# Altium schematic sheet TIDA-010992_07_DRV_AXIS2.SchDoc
size 431 x 279 mm; Date: Not shown in title block; ApprovedBy: Not shown in title block; CheckedBy: Not shown in title block; Author: Not shown in title block; CompanyName: Not shown in title block; Engineer: Not shown in title block; Organization: Not shown in title block; Address1: Not shown in title block; Address2: Not shown in title block; Address3: Not shown in title block; Address4: Not shown in title block; DocumentNumber: 7; Revision: Use project parameter SCH_Rev; SheetNumber: 7; SheetTotal: 13; PageSetup: Record=PageOptions¦CenterHorizontal=True¦CenterVertical=True¦PrintScale=1.00¦XCorrection=1.00¦YCorrection=1.00¦PrintKind=0¦BorderSize=5000000¦LeftOffset=0¦BottomOffset=0¦Orientation=2¦PaperLength=1000¦PaperWidth=1000¦Scale=100¦PaperSource=15¦PrintQuality=600¦MediaType=1¦DitherType=10¦PaperKind=Letter¦PrintScaleMode=1
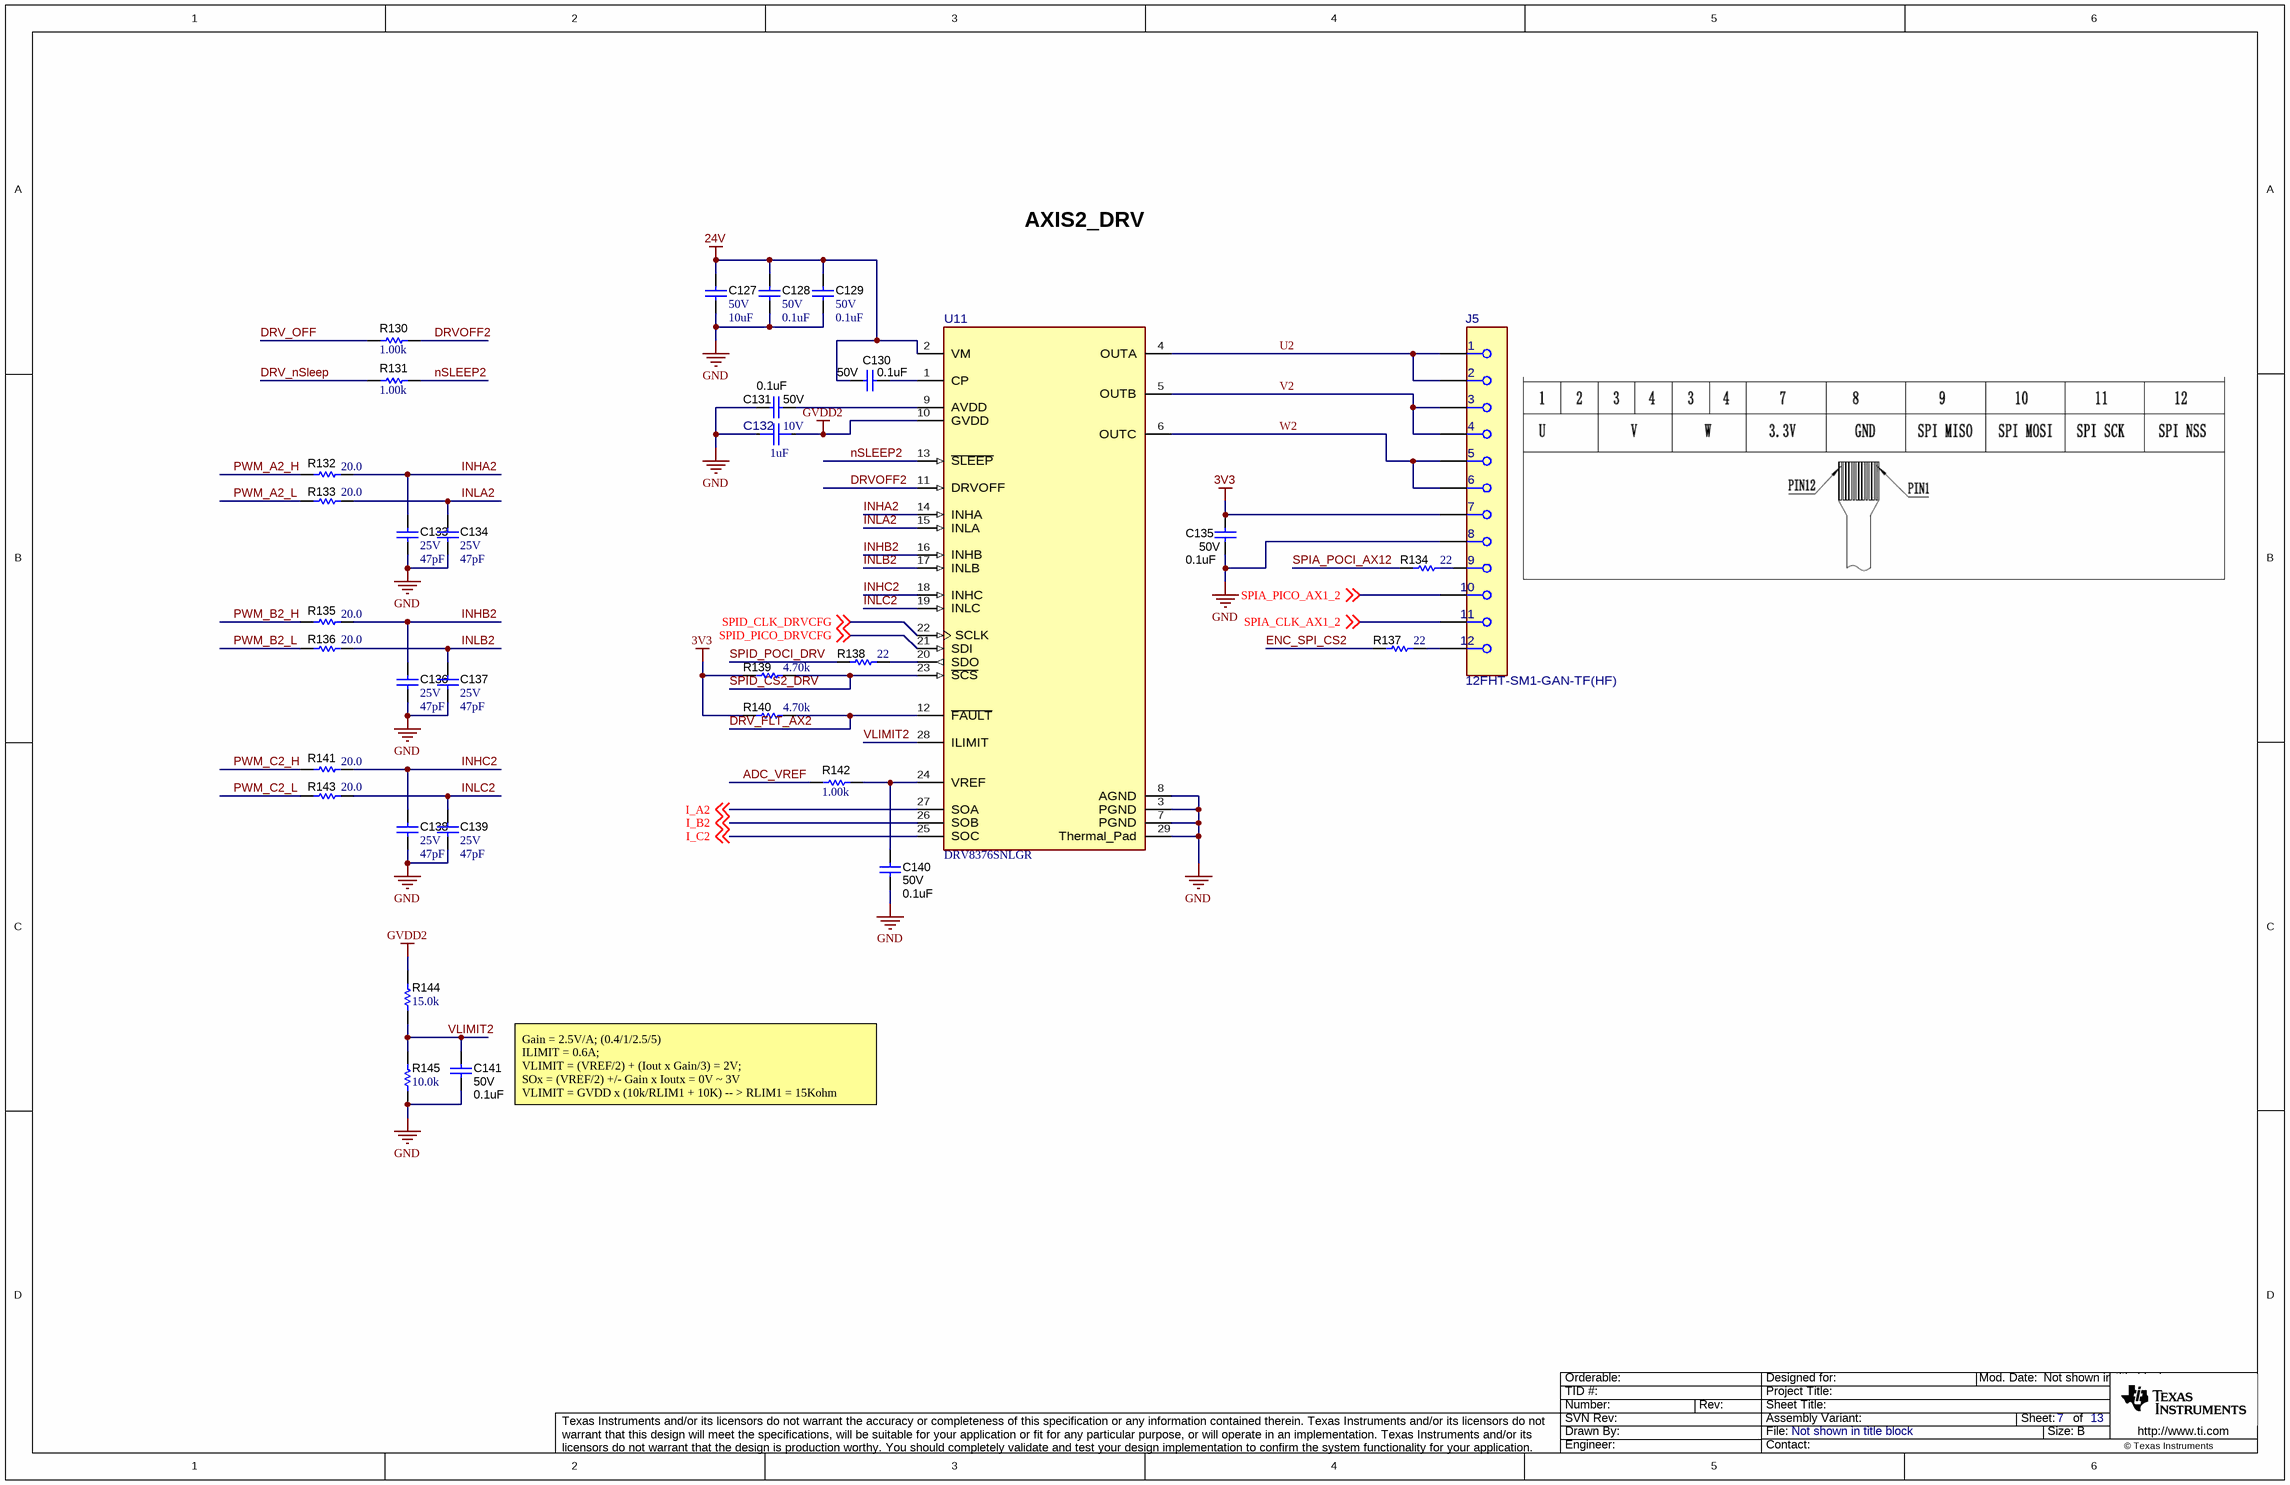
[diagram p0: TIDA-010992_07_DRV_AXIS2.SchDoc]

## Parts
C127  VDC_V: 50V  ValueDisplayed: 10uF  [1206_180]  (hidden comment: CL31B106KBHNNNE)
C128  VDC_V: 50V  ValueDisplayed: 0.1uF  [0402]  (hidden comment: C1005X7R1H104K050BE)
C129  VDC_V: 50V  ValueDisplayed: 0.1uF  [0402]  (hidden comment: C1005X7R1H104K050BE)
C130  VDC_V: 50V  ValueDisplayed: 0.1uF  [0402]  (hidden comment: CGA2B3X7R1H104M050BB)
C131  VDC_V: 50V  ValueDisplayed: 0.1uF  [0402]  (hidden comment: CGA2B3X7R1H104M050BB)
C132  VDC_V: 10V  ValueDisplayed: 1uF  [FP-GMC04X7R105K10NT_0402-MFG]  (hidden comment: GMC04X7R105K10NT)
C133  VDC_V: 25V  ValueDisplayed: 47pF  [0201_033]  (hidden comment: GRM0335C1E470JA01D)
C134  VDC_V: 25V  ValueDisplayed: 47pF  [0201_033]  (hidden comment: GRM0335C1E470JA01D)
C135  VDC_V: 50V  ValueDisplayed: 0.1uF  [0402]  (hidden comment: CGA2B3X7R1H104M050BB)
C136  VDC_V: 25V  ValueDisplayed: 47pF  [0201_033]  (hidden comment: GRM0335C1E470JA01D)
C137  VDC_V: 25V  ValueDisplayed: 47pF  [0201_033]  (hidden comment: GRM0335C1E470JA01D)
C138  VDC_V: 25V  ValueDisplayed: 47pF  [0201_033]  (hidden comment: GRM0335C1E470JA01D)
C139  VDC_V: 25V  ValueDisplayed: 47pF  [0201_033]  (hidden comment: GRM0335C1E470JA01D)
C140  VDC_V: 50V  ValueDisplayed: 0.1uF  [0402]  (hidden comment: CGA2B3X7R1H104M050BB)
C141  VDC_V: 50V  ValueDisplayed: 0.1uF  [0402]  (hidden comment: CGA2B3X7R1H104M050BB)
J5  12FHT-SM1-GAN-TF(HF)  [FP-12FHT-SM1-GAN-TF(HF)_CONN_FPC_12-MFG]
R130  ValueDisplayed: 1.00k  [0402]  (hidden comment: CRCW04021K00FKED)
R131  ValueDisplayed: 1.00k  [0402]  (hidden comment: CRCW04021K00FKED)
R132  ValueDisplayed: 20.0  [0201_033]  (hidden comment: CRCW020120R0FNED)
R133  ValueDisplayed: 20.0  [0201_033]  (hidden comment: CRCW020120R0FNED)
R134  ValueDisplayed: 22  [0201]  (hidden comment: ERJ-1GNJ220C)
R135  ValueDisplayed: 20.0  [0201_033]  (hidden comment: CRCW020120R0FNED)
R136  ValueDisplayed: 20.0  [0201_033]  (hidden comment: CRCW020120R0FNED)
R137  ValueDisplayed: 22  [0201]  (hidden comment: ERJ-1GNJ220C)
R138  ValueDisplayed: 22  [0201]  (hidden comment: ERJ-1GNJ220C)
R139  ValueDisplayed: 4.70k  [0201]  (hidden comment: RC0201FR-7D4K7L)
R140  ValueDisplayed: 4.70k  [0201]  (hidden comment: RC0201FR-7D4K7L)
R141  ValueDisplayed: 20.0  [0201_033]  (hidden comment: CRCW020120R0FNED)
R142  ValueDisplayed: 1.00k  [0402]  (hidden comment: CRCW04021K00FKED)
R143  ValueDisplayed: 20.0  [0201_033]  (hidden comment: CRCW020120R0FNED)
R144  ValueDisplayed: 15.0k  [0402]  (hidden comment: RC0402FR-0715KL)
R145  ValueDisplayed: 10.0k  [0402L]  (hidden comment: CRCW040210K0FKED)
U11  DRV8376SNLGR  [NLG0028A-MFG]

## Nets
3V3: C135.2 J5.7 R139.2 R140.2
24V: C127.1 C128.1 C129.1 C130.1 U11.2(VM)
GND: C127.2 C128.2 C129.2 C131.1 C132.1 C133.2 C134.2 C135.1 C136.2 C137.2 C138.2 C139.2 C140.1 C141.1 J5.8 R145.1 U11.3(PGND) U11.7(PGND) U11.8(AGND) U11.29(Thermal_Pad)
GVDD2: C132.2 R144.2 U11.10(GVDD)
ADC_VREF: R142.1
DRV_FLT_AX2: R140.1 U11.12(~{FAULT})
DRV_nSleep: R131.1
DRV_OFF: R130.1
DRVOFF2: R130.2 U11.11(DRVOFF)
ENC_SPI_CS2: R137.1
I_A2: U11.27(SOA) ; off-sheet I_A2
I_B2: U11.26(SOB) ; off-sheet I_B2
I_C2: U11.25(SOC) ; off-sheet I_C2
INHA2: C133.1 R132.2 U11.14(INHA)
INHB2: C136.1 R135.2 U11.16(INHB)
INHC2: C138.1 R141.2 U11.18(INHC)
INLA2: C134.1 R133.2 U11.15(INLA)
INLB2: C137.1 R136.2 U11.17(INLB)
INLC2: C139.1 R143.2 U11.19(INLC)
nSLEEP2: R131.2 U11.13(~{SLEEP})
PWM_A2_H: R132.1
PWM_A2_L: R133.1
PWM_B2_H: R135.1
PWM_B2_L: R136.1
PWM_C2_H: R141.1
PWM_C2_L: R143.1
SPIA_CLK_AX1_2: J5.11 ; off-sheet SPIA_CLK_AX1_2
SPIA_PICO_AX1_2: J5.10 ; off-sheet SPIA_PICO_AX1_2
SPIA_POCI_AX12: R134.1
SPID_CLK_DRVCFG: U11.22(SCLK) ; off-sheet SPID_CLK_DRVCFG
SPID_CS2_DRV: R139.1 U11.23(~{SCS})
SPID_PICO_DRVCFG: U11.21(SDI) ; off-sheet SPID_PICO_DRVCFG
SPID_POCI_DRV: R138.1
U2: J5.1 J5.2 U11.4(OUTA)
V2: J5.3 J5.4 U11.5(OUTB)
VLIMIT2: C141.2 R144.1 R145.2 U11.28(ILIMIT)
W2: J5.5 J5.6 U11.6(OUTC)
NetC130_2: C130.2 U11.1(CP)
NetC131_2: C131.2 U11.9(AVDD)
NetC140_2: C140.2 R142.2 U11.24(VREF)
NetJ5_9: J5.9 R134.2
NetJ5_12: J5.12 R137.2
NetR138_2: R138.2 U11.20(SDO)

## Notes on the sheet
- AXIS2_DRV
- Gain = 2.5V/A; (0.4/1/2.5/5)
  ILIMIT = 0.6A;
  VLIMIT = (VREF/2) + (Iout x Gain/3) = 2V;
  SOx = (VREF/2) +/- Gain x Ioutx = 0V ~ 3V
  VLIMIT = GVDD x (10k/RLIM1 + 10K) -- > RLIM1 = 15Kohm

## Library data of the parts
C127 = CMP-0008802-2: CAP, CERM, 10 uF, 50 V, +/- 10%, X7R, 1206; Manufacturer: Samsung; TaMin_C: -55°C; Polarized: N; SizeAreaWB_mm2: 10.92; Value1: Unknown; U/M: EA; Value: 10uF; TaMax_C: 125°C; SizeZ_mm: 1.8; SizeX_mm: 3.2; SizeY_mm: 1.6; Cap_Case: 1206; SizeArea_mm2: 5.12; Cap_F: 10µF; AEC Category: Q200
C128 C129 = CMP-0064946-2: CAP, CERM, 0.1 uF, 50 V,+/- 10%, X7R, 0402; Manufacturer: TDK; TaMin_C: -55°C; Polarized: N; SizeAreaWB_mm2: 3; Value1: Unknown; U/M: EA; Value: 0.1uF; TaMax_C: 125°C; SizeZ_mm: 0.6; SizeX_mm: 1; SizeY_mm: 0.5; Cap_F: 100nF; AEC Category: Q200
C130 C131 C135 C140 C141 = CMP-0006326-2: CAP, CERM, 0.1 uF, 50 V, +/- 20%, X7R, AEC-Q200 Grade 1, 0402; Manufacturer: TDK; TaMin_C: -55°C; Polarized: N; SizeAreaWB_mm2: 3; Value1: Unknown; U/M: EA; Value: 0.1uF; TaMax_C: 125°C; SizeZ_mm: 0.6; SizeX_mm: 1; SizeY_mm: 0.5; AEC Qualified: Y; Cap_F: 100nF; AEC Category: Q200
C132 = CMP-0093200-1: 1µF ±10% 10V Ceramic Capacitor X7R 0402 (1005 Metric); Manufacturer: Cal-Chip Electronics; TempCo: 15%; SizeZ_mm: 0.6mm; AEC Qualified: No
C133 C134 C136-C139 = CMP-0009662-3: CAP, CERM, 47 pF, 25 V, +/- 5%, C0G/NP0, 0201; Manufacturer: MuRata; TaMin_C: -55°C; Polarized: N; SizeAreaWB_mm2: 2.08; Value1: Unknown; U/M: EA; Value: 47pF; TaMax_C: 125°C; SizeZ_mm: 0.33; SizeX_mm: 0.6; SizeY_mm: 0.3; Cap_Case: 0201; SizeArea_mm2: 0.18; AEC Category: Q200
J5 = CMP-0126588-1: Conn FPC Connector F 12 POS 0.5mm Solder Ver SMD T/R; Manufacturer: JST; ContactFinish: Gold,Nickel; Current_A: 500mA; Voltage_V: 50V; AEC Qualified: No; Conn Gender: Female; Conn Orientation: Vertical; Is Female: yes; SizeZ_mm: 3.3mm; Standoff Height: 0.13mm
R130 R131 R142 = CMP-0026071-3: RES, 1.00 k, 1%, 0.063 W, AEC-Q200 Grade 0, 0402; Manufacturer: Vishay-Dale; Power_W: 63mW; TempCo: 100 ppm/C; Value_Code: 1k00; Value: 1.00k; EIA_Code: E96; Res_ohm: 1k; SizeX_mm: 1; SizeY_mm: 0.5; SizeZ_mm: 0.6; Value2: 0.063W; AEC Qualified: Y; VDC_V: 50V; AEC Category: Q200; AEC Grade: 0
R132 R133 R135 R136 R141 R143 = CMP-0078192-1: RES, 20.0, 1%, 0.05 W, 0201; Manufacturer: Vishay-Dale; Value_Code: 20R0; SizeArea_mm2: 0.18; AEC Qualified: N; AEC Category: Q200; Res_ohm: 20; Value: 20.0; SizeZ_mm: 0.33; EIA_Code: E96; TempCo: 200 ppm/C; Power_W: 50mW; VDC_V: 30V; SizeY_mm: 0.3; Value2: 0.05W; U/M: EA; SizeX_mm: 0.6
R134 R137 R138 = CMP-0027015-3: RES, 22, 5%, 0.05 W, AEC-Q200 Grade 1, 0201; Manufacturer: Panasonic; Power_W: 50mW; TempCo: 200 ppm/C; Value_Code: 22R0; U/M: EA; Value: 22; EIA_Code: E24; SizeX_mm: 0.6; SizeY_mm: 0.3; SizeZ_mm: 0.26; Value2: 0.05W; SizeArea_mm2: 0.18; AEC Qualified: Y; AEC Grade: 1; AEC Category: Q200
R139 R140 = CMP-0028031-1: RES, 4.70 k, 1%, 0.05 W, 0201; Manufacturer: Yageo America; Power_W: 50mW; TempCo: 200 ppm/C; Value_Code: 4k70; U/M: EA; Value: 4.70k; Res_ohm: 4.7k; SizeX_mm: 0.6; SizeY_mm: 0.3; SizeZ_mm: 0.26; Value2: 0.05W; SizeArea_mm2: 0.18; AEC Qualified: N; VDC_V: 25V; AEC Category: Q200
R144 = CMP-0078583-1: RES, 15.0 k, 1%, 0.063 W, 0402; Manufacturer: Yageo America; Power_W: 63mW; Green_Lifecycle: Active; TempCo: 100 ppm/C; Value_Code: 15k0; Green_REACh: Passed; Value: 15.0k; EIA_Code: E96; Res_ohm: 15k; SizeX_mm: 1; SizeY_mm: 0.5; SizeZ_mm: 0.6; Value2: 0.063W; AEC Qualified: N; AEC Category: Q200
R145 = CMP-0025958-3: RES, 10.0 k, 1%, 0.063 W, AEC-Q200 Grade 0, 0402; Manufacturer: Vishay-Dale; Power_W: 63mW; TempCo: 100 ppm/C; Value_Code: 10k0; Value: 10.0k; EIA_Code: E96; Res_ohm: 10k; SizeX_mm: 1; SizeY_mm: 0.5; SizeZ_mm: 0.6; Value2: 0.063W; AEC Qualified: Y; VDC_V: 50V; AEC Category: Q200; AEC Grade: 0
U11 = CMP-0122073-1: Three-Phase Integrated FET Motor Driver; Manufacturer: Texas Instruments; SizeZ_mm: 1mm; AEC Qualified: No; Max Supply Voltage: 65V; Min Supply Voltage: 4.5V; Motor Type: Brushless DC; Nominal Supply Current: 6.6-8.2mA; Number Of Outputs: 3; Standoff Height: 0mm; Switching Frequency: 100kHz; TaMax_C: +125°C; TaMin_C: -40°C; TJmax_C: +150°C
